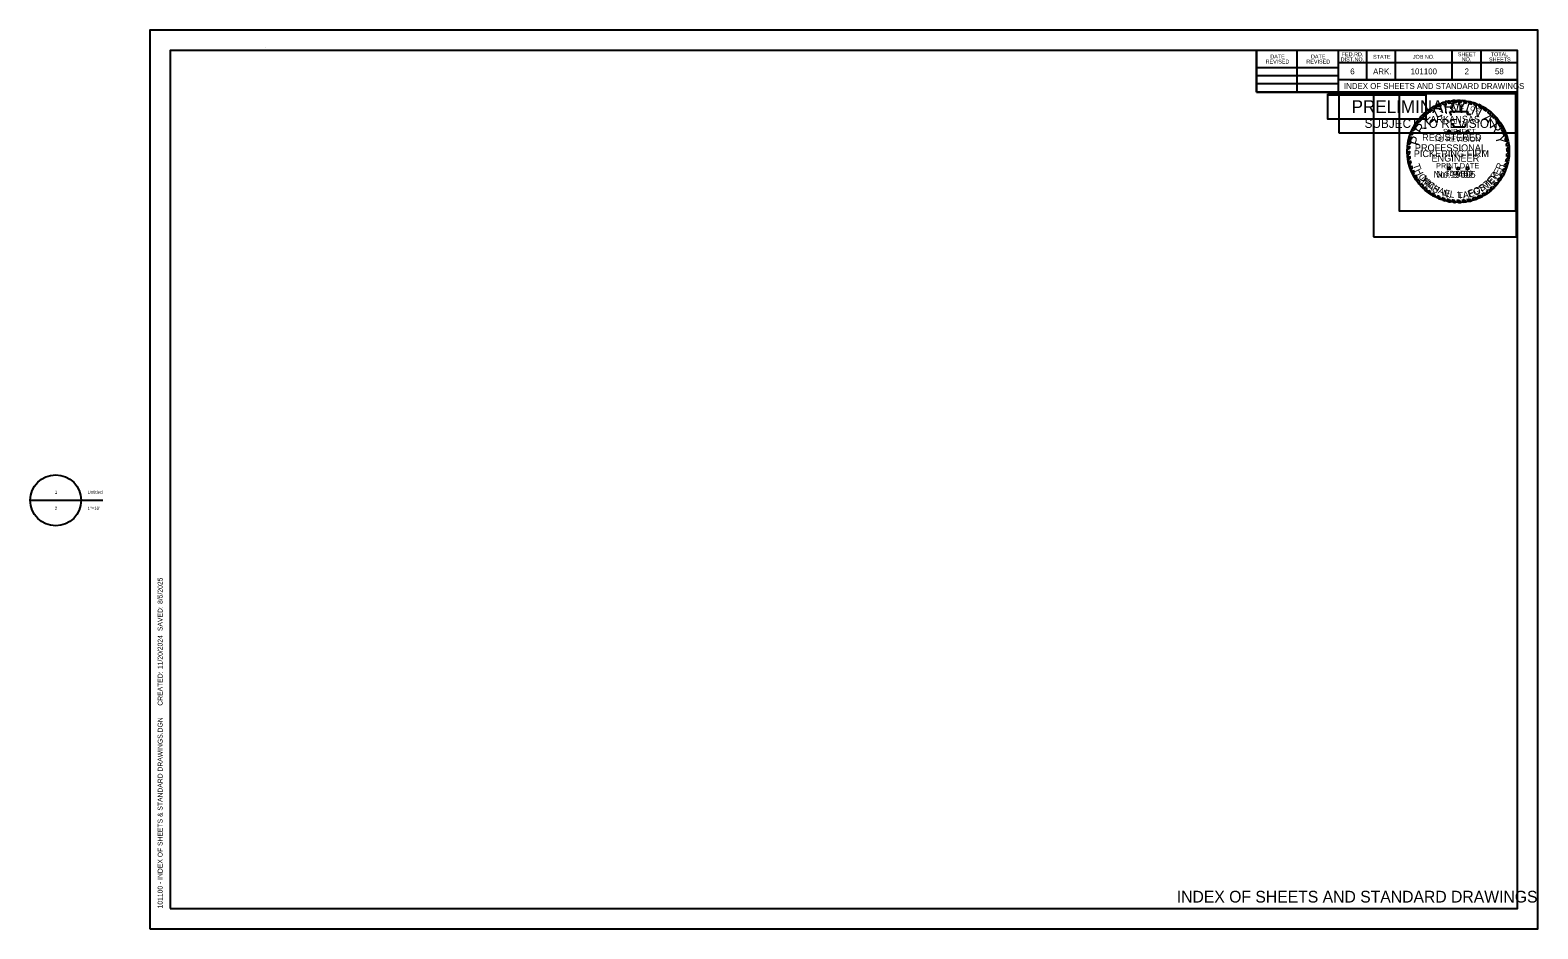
# Model space of a CAD drawing. Extents: x -0.12 to 1.42, y 0 to 0.92.
import ezdxf

# ---------------------------------------------------------------- set-up
doc = ezdxf.new("R2010")
doc.units = 0
for name, color, linetype in [('Default', 7, 'Continuous'), ('DSN_DRFT_Guideline-No-Plot', 7, 'Continuous'), ('SHET_Annotations', 7, 'Continuous'), ('SHET_Border-Lines', 7, 'Continuous'), ('SHET_Border-Text', 7, 'Continuous'), ('SHET_Stamp-Prelim', 7, 'Continuous'), ('SHET_Stamp-Seal', 7, 'Continuous'), ('STAMP_PE DIG SIG', 7, 'Continuous'), ('STAMP_PE_BACKGROUND', 7, 'Continuous'), ('STAMP_PE_FOSTER', 7, 'Continuous'), ('STAMP_PE_SEAL-INFO', 7, 'Continuous'), ('STAMP_PE_TAEGTMEYER', 7, 'Continuous'), ('STAMP_PRELIMINARY', 7, 'Continuous')]:
    doc.layers.add(name, color=color, linetype=linetype)

msp = doc.modelspace()

# ---------------------------------------------------------------- linework, layer by layer
at = {"layer": 'Default'}
for p, q in [((-0.1223, 0.4371), (-0.0702, 0.4371)), ((-0.096, 0.4371), (-0.0481, 0.4371))]:
    msp.add_line(p, q, dxfattribs=at)
msp.add_circle((-0.0962, 0.4371), 0.026, dxfattribs=at)
at = {"layer": 'DSN_DRFT_Guideline-No-Plot'}
msp.add_lwpolyline([(0, 0), (1.4167, 0), (1.4167, 0.9167), (0, 0.9167)], close=True, dxfattribs=at)
at = {"layer": 'SHET_Border-Lines'}
for p, q in [((0.1176, 0.8988), (0.1176, 0.8988)), ((0.1176, 0.8988), (0.1176, 0.8988)), ((1.1296, 0.8534), (1.1296, 0.8958)), ((1.1711, 0.8534), (1.1711, 0.8958)), ((1.2127, 0.8958), (1.2127, 0.8534)), ((1.2417, 0.8958), (1.2417, 0.866)), ((1.2712, 0.8958), (1.2712, 0.866)), ((1.3289, 0.8958), (1.3289, 0.866)), ((1.3584, 0.8958), (1.3584, 0.866)), ((1.1296, 0.8786), (1.2127, 0.8786)), ((1.3958, 0.8832), (1.2127, 0.8832)), ((1.3958, 0.8833), (1.3958, 0.8833)), ((1.1296, 0.8706), (1.2127, 0.8706)), ((1.1296, 0.8622), (1.2127, 0.8622)), ((1.3958, 0.866), (1.2127, 0.866)), ((1.2252, 0.866), (1.3958, 0.866)), ((1.3958, 0.8534), (1.1296, 0.8534))]:
    msp.add_line(p, q, dxfattribs=at)
for points in [[(0.0208, 0.0208), (1.3958, 0.0208), (1.3958, 0.8958), (0.0208, 0.8958)], [(1.1296, 0.8534), (1.3958, 0.8534), (1.3958, 0.8958), (1.1296, 0.8958)]]:
    msp.add_lwpolyline(points, close=True, dxfattribs=at)
at = {"layer": 'SHET_Stamp-Prelim'}
msp.add_lwpolyline([(1.2137, 0.8119), (1.3948, 0.8119), (1.3948, 0.8524), (1.2137, 0.8524)], close=True, dxfattribs=at)
at = {"layer": 'SHET_Stamp-Seal'}
msp.add_line((1.3219, 0.7895), (1.3219, 0.7895), dxfattribs=at)
msp.add_lwpolyline([(1.249, 0.7057), (1.3948, 0.7057), (1.3948, 0.8524), (1.249, 0.8524)], close=True, dxfattribs=at)
at = {"layer": 'STAMP_PE DIG SIG'}
msp.add_lwpolyline([(1.2022, 0.8508), (1.3022, 0.8508), (1.3022, 0.8258), (1.2022, 0.8258)], close=True, dxfattribs=at)
at = {"layer": 'STAMP_PE_BACKGROUND'}
for points in [[(1.2022, 0.8517), (1.3022, 0.8517), (1.3022, 0.8258), (1.2022, 0.8258)], [(1.3942, 0.8517), (1.275, 0.8517), (1.275, 0.7325), (1.3942, 0.7325)]]:
    msp.add_lwpolyline(points, close=True, dxfattribs=at)
at = {"layer": 'STAMP_PE_SEAL-INFO'}
for p, q in [((1.3002, 0.8313), (1.3028, 0.8306)), ((1.3021, 0.833), (1.3051, 0.8325)), ((1.3042, 0.8348), (1.3068, 0.8337)), ((1.3066, 0.8363), (1.309, 0.8352)), ((1.3087, 0.8377), (1.3112, 0.8365)), ((1.3112, 0.8391), (1.3138, 0.8378)), ((1.3137, 0.8403), (1.3158, 0.8387)), ((1.3165, 0.8415), (1.3181, 0.8397)), ((1.3184, 0.8422), (1.3206, 0.8405)), ((1.3217, 0.8432), (1.3233, 0.8413)), ((1.3239, 0.8438), (1.3259, 0.8418)), ((1.3266, 0.8443), (1.3283, 0.8422)), ((1.3269, 0.8337), (1.3456, 0.8337)), ((1.3276, 0.832), (1.3269, 0.8337)), ((1.3281, 0.8303), (1.3276, 0.832)), ((1.3295, 0.8447), (1.331, 0.8426)), ((1.3336, 0.8427), (1.3318, 0.8449)), ((1.3364, 0.8428), (1.3348, 0.845)), ((1.3389, 0.8426), (1.3375, 0.845)), ((1.3417, 0.8424), (1.3401, 0.8448)), ((1.3441, 0.842), (1.3427, 0.8445)), ((1.3456, 0.8337), (1.3443, 0.831)), ((1.3473, 0.8413), (1.3463, 0.8439)), ((1.3495, 0.8407), (1.3486, 0.8433)), ((1.352, 0.8399), (1.3512, 0.8426)), ((1.3544, 0.839), (1.3536, 0.8418)), ((1.357, 0.8379), (1.3564, 0.8406)), ((1.3594, 0.8366), (1.359, 0.8394)), ((1.3616, 0.8353), (1.3614, 0.8381)), ((1.364, 0.8337), (1.3639, 0.8366)), ((1.366, 0.8322), (1.3662, 0.8349)), ((1.3685, 0.8301), (1.3687, 0.8331)), ((1.3703, 0.8285), (1.3707, 0.8313)), ((1.2891, 0.8167), (1.2918, 0.8171)), ((1.2904, 0.8191), (1.2931, 0.8192)), ((1.2917, 0.8213), (1.2946, 0.8215)), ((1.293, 0.8232), (1.2959, 0.8232)), ((1.2946, 0.8253), (1.2977, 0.8254)), ((1.2965, 0.8276), (1.2994, 0.8274)), ((1.2983, 0.8295), (1.3014, 0.8293)), ((1.3282, 0.8297), (1.3281, 0.8303)), ((1.3293, 0.8201), (1.3291, 0.8213)), ((1.331, 0.8201), (1.3293, 0.8201)), ((1.331, 0.8177), (1.331, 0.8201)), ((1.3423, 0.8177), (1.331, 0.8177)), ((1.3424, 0.8196), (1.3423, 0.8177)), ((1.3429, 0.8213), (1.3424, 0.8196)), ((1.3443, 0.831), (1.3478, 0.831)), ((1.3478, 0.831), (1.347, 0.8297)), ((1.3723, 0.8264), (1.3727, 0.8294)), ((1.3738, 0.8247), (1.3746, 0.8273)), ((1.3756, 0.8223), (1.3764, 0.8251)), ((1.3769, 0.8206), (1.3779, 0.8232)), ((1.3786, 0.8178), (1.3796, 0.8205)), ((1.3797, 0.8157), (1.381, 0.8182)), ((1.381, 0.813), (1.3823, 0.8157)), ((1.2862, 0.8008), (1.2838, 0.7996)), ((1.2867, 0.8034), (1.2841, 0.802)), ((1.2847, 0.8048), (1.2873, 0.8059)), ((1.2853, 0.8071), (1.2879, 0.808)), ((1.2862, 0.8099), (1.2889, 0.8106)), ((1.287, 0.8121), (1.2898, 0.8129)), ((1.288, 0.8145), (1.2908, 0.8151)), ((1.3252, 0.8129), (1.3241, 0.8137)), ((1.3241, 0.8137), (1.3255, 0.8137)), ((1.3248, 0.8116), (1.3252, 0.8129)), ((1.3259, 0.8124), (1.3248, 0.8116)), ((1.3255, 0.8137), (1.3259, 0.815)), ((1.3259, 0.815), (1.3264, 0.8137)), ((1.327, 0.8116), (1.3259, 0.8124)), ((1.3264, 0.8137), (1.3277, 0.8137)), ((1.3277, 0.8137), (1.3266, 0.8129)), ((1.3266, 0.8129), (1.327, 0.8116)), ((1.3347, 0.8129), (1.3336, 0.8137)), ((1.3336, 0.8137), (1.335, 0.8137)), ((1.3343, 0.8116), (1.3347, 0.8129)), ((1.3354, 0.8124), (1.3343, 0.8116)), ((1.335, 0.8137), (1.3354, 0.815)), ((1.3354, 0.815), (1.3358, 0.8137)), ((1.3365, 0.8116), (1.3354, 0.8124)), ((1.3358, 0.8137), (1.3372, 0.8137)), ((1.3372, 0.8137), (1.3361, 0.8129)), ((1.3361, 0.8129), (1.3365, 0.8116)), ((1.3442, 0.8129), (1.3431, 0.8137)), ((1.3431, 0.8137), (1.3445, 0.8137)), ((1.3438, 0.8116), (1.3442, 0.8129)), ((1.3449, 0.8124), (1.3438, 0.8116)), ((1.3445, 0.8137), (1.3449, 0.815)), ((1.3449, 0.815), (1.3453, 0.8137)), ((1.346, 0.8116), (1.3449, 0.8124)), ((1.3453, 0.8137), (1.3467, 0.8137)), ((1.3467, 0.8137), (1.3456, 0.8129)), ((1.3456, 0.8129), (1.346, 0.8116)), ((1.3818, 0.8112), (1.3832, 0.8136)), ((1.3829, 0.8081), (1.3844, 0.8107)), ((1.3835, 0.8061), (1.3851, 0.8086)), ((1.3842, 0.8029), (1.386, 0.8054)), ((1.3846, 0.8008), (1.3866, 0.8028)), ((1.2857, 0.796), (1.2834, 0.7946)), ((1.2856, 0.7933), (1.2834, 0.7914)), ((1.2859, 0.7984), (1.2835, 0.7968)), ((1.2857, 0.791), (1.2835, 0.7892)), ((1.2858, 0.7882), (1.2838, 0.7862)), ((1.2861, 0.7858), (1.2842, 0.7837)), ((1.3846, 0.7855), (1.3871, 0.7867)), ((1.3849, 0.7876), (1.3874, 0.7891)), ((1.385, 0.798), (1.387, 0.7998)), ((1.3851, 0.7956), (1.3873, 0.7973)), ((1.3852, 0.7927), (1.3875, 0.7945)), ((1.3852, 0.7905), (1.3875, 0.792)), ((1.2866, 0.7833), (1.2847, 0.7812)), ((1.2871, 0.7809), (1.2854, 0.7786)), ((1.2878, 0.7784), (1.2861, 0.7761)), ((1.2886, 0.7761), (1.287, 0.7738)), ((1.2895, 0.7737), (1.288, 0.7713)), ((1.2905, 0.7715), (1.2892, 0.769)), ((1.3252, 0.7754), (1.3241, 0.7763)), ((1.3241, 0.7763), (1.3255, 0.7763)), ((1.3248, 0.7741), (1.3252, 0.7754)), ((1.3259, 0.7749), (1.3248, 0.7741)), ((1.3255, 0.7763), (1.3259, 0.7776)), ((1.3259, 0.7776), (1.3264, 0.7763)), ((1.327, 0.7741), (1.3259, 0.7749)), ((1.3264, 0.7763), (1.3277, 0.7763)), ((1.3277, 0.7763), (1.3266, 0.7754)), ((1.3266, 0.7754), (1.327, 0.7741)), ((1.3347, 0.7754), (1.3336, 0.7763)), ((1.3336, 0.7763), (1.335, 0.7763)), ((1.3343, 0.7741), (1.3347, 0.7754)), ((1.3354, 0.7749), (1.3343, 0.7741)), ((1.335, 0.7763), (1.3354, 0.7776)), ((1.3354, 0.7776), (1.3358, 0.7763)), ((1.3365, 0.7741), (1.3354, 0.7749)), ((1.3358, 0.7763), (1.3372, 0.7763)), ((1.3372, 0.7763), (1.3361, 0.7754)), ((1.3361, 0.7754), (1.3365, 0.7741)), ((1.3442, 0.7754), (1.3431, 0.7763)), ((1.3431, 0.7763), (1.3445, 0.7763)), ((1.3438, 0.7741), (1.3442, 0.7754)), ((1.3449, 0.7749), (1.3438, 0.7741)), ((1.3445, 0.7763), (1.3449, 0.7776)), ((1.3449, 0.7776), (1.3453, 0.7763)), ((1.346, 0.7741), (1.3449, 0.7749)), ((1.3453, 0.7763), (1.3467, 0.7763)), ((1.3467, 0.7763), (1.3456, 0.7754)), ((1.3456, 0.7754), (1.346, 0.7741)), ((1.3799, 0.7705), (1.3826, 0.7709)), ((1.3808, 0.7724), (1.3835, 0.7729)), ((1.382, 0.7753), (1.3847, 0.776)), ((1.3827, 0.7774), (1.3855, 0.7785)), ((1.3835, 0.7802), (1.3862, 0.7813)), ((1.3841, 0.7827), (1.3867, 0.7838)), ((1.2918, 0.769), (1.2907, 0.7662)), ((1.2931, 0.7667), (1.2921, 0.7641)), ((1.2942, 0.765), (1.2936, 0.7619)), ((1.2958, 0.7628), (1.2952, 0.7598)), ((1.2975, 0.7607), (1.297, 0.7578)), ((1.2992, 0.7588), (1.2988, 0.7559)), ((1.301, 0.757), (1.3008, 0.754)), ((1.3029, 0.7552), (1.3029, 0.7523)), ((1.3679, 0.7553), (1.3706, 0.7545)), ((1.3702, 0.7573), (1.3727, 0.7566)), ((1.3716, 0.7588), (1.3743, 0.7583)), ((1.3738, 0.7612), (1.3763, 0.7608)), ((1.3755, 0.7634), (1.3783, 0.7634)), ((1.3774, 0.7662), (1.3801, 0.7661)), ((1.3783, 0.7677), (1.3811, 0.768)), ((1.3049, 0.7536), (1.305, 0.7507)), ((1.3068, 0.7522), (1.307, 0.7493)), ((1.3092, 0.7506), (1.3095, 0.7478)), ((1.3111, 0.7495), (1.3117, 0.7466)), ((1.3138, 0.7481), (1.3147, 0.7452)), ((1.3159, 0.7471), (1.3169, 0.7443)), ((1.3187, 0.7461), (1.3198, 0.7433)), ((1.321, 0.7453), (1.3222, 0.7426)), ((1.3238, 0.7445), (1.325, 0.7419)), ((1.326, 0.7441), (1.3274, 0.7415)), ((1.3288, 0.7436), (1.3302, 0.7411)), ((1.3313, 0.7433), (1.3328, 0.7409)), ((1.334, 0.7432), (1.3356, 0.7409)), ((1.3365, 0.7432), (1.3384, 0.741)), ((1.3394, 0.7433), (1.3412, 0.7412)), ((1.3419, 0.7436), (1.344, 0.7416)), ((1.3444, 0.744), (1.3465, 0.7421)), ((1.3471, 0.7446), (1.3492, 0.7427)), ((1.3497, 0.7453), (1.352, 0.7436)), ((1.3524, 0.7462), (1.3549, 0.7447)), ((1.3548, 0.7471), (1.3571, 0.7456)), ((1.3573, 0.7483), (1.36, 0.7471)), ((1.3596, 0.7494), (1.3619, 0.7481)), ((1.3619, 0.7508), (1.3644, 0.7497)), ((1.3639, 0.7521), (1.3663, 0.751)), ((1.3664, 0.754), (1.369, 0.7532))]:
    msp.add_line(p, q, dxfattribs=at)
for radius, start, end in [(0.0521, 129.7326, 132.5376), (0.0498, 127.5297, 130.9683), (0.0521, 123.6199, 126.5906), (0.0498, 121.9746, 125.11), (0.0521, 117.6544, 120.8099), (0.0498, 115.6869, 119.1583), (0.0521, 111.3124, 114.7026), (0.0498, 110.3086, 113.1659), (0.0521, 105.2339, 109.0352), (0.0498, 104.0352, 107.3615), (0.0521, 99.7525, 102.7765), (0.0498, 98.258, 101.0329), (0.0521, 93.9381, 96.5517), (0.0498, 92.1102, 95.0367), (0.0521, 87.7298, 90.6707), (0.0498, 85.9628, 88.9097), (0.0521, 81.9732, 84.8236), (0.0498, 79.9264, 82.696), (0.0521, 75.3125, 77.9426), (0.0498, 73.5575, 76.2314), (0.0521, 69.6061, 72.3058), (0.0498, 67.6248, 70.504), (0.0521, 63.1329, 66.2704), (0.0498, 61.1558, 64.3784), (0.0521, 56.9003, 60.0942), (0.0498, 54.9238, 58.2702), (0.0498, 48.3016, 52.0395), (0.0521, 50.3492, 53.7159), (0.0521, 44.3405, 47.3929), (0.0521, 152.864, 155.5189), (0.0521, 147.0072, 149.899), (0.0498, 151.0315, 153.573), (0.0521, 141.6056, 144.4486), (0.0498, 145.0197, 148.2104), (0.0498, 139.301, 142.5873), (0.0521, 135.4021, 138.3031), (0.0498, 133.1331, 136.2562), (0.0498, 42.2212, 45.5512), (0.0498, 36.135, 39.5311), (0.0521, 38.1247, 41.2316), (0.0498, 29.9032, 33.6645), (0.0521, 31.9614, 35.4294), (0.0498, 23.7732, 27.2211), (0.0521, 25.9391, 29.0125), (0.0521, 170.0003, 172.6878), (0.0521, 164.3068, 166.894), (0.0521, 158.4077, 161.0701), (0.0498, 167.9048, 170.9039), (0.0498, 162.4331, 165.0013), (0.0498, 156.3402, 159.2319), (0.0498, 17.6802, 21.4251), (0.0521, 19.9538, 23.3141), (0.0498, 11.5444, 15.2364), (0.0498, 5.7599, 9.0606), (0.0521, 13.8421, 17.4447), (0.0521, 7.5852, 10.8621), (0.0521, 175.7409, 178.2066), (0.0521, 181.7251, 184.1626), (0.0521, 187.4204, 190.1927), (0.0498, 179.6454, 182.2633), (0.0498, 173.73, 176.4734), (0.0498, 185.4539, 188.234), (0.0498, 348.0778, 351.3435), (0.0498, 353.8632, 357.1274), (0.0498, 359.7329, 3.0639), (0.0521, 349.8305, 353.0885), (0.0521, 1.7215, 4.7268), (0.0521, 355.7156, 358.9569), (0.0521, 193.0369, 195.9973), (0.0521, 198.8967, 201.6281), (0.0498, 191.2274, 193.9858), (0.0498, 196.9675, 199.8353), (0.0521, 204.5479, 207.4328), (0.0498, 202.7761, 205.4791), (0.0498, 329.5549, 333.2076), (0.0498, 335.6038, 339.1858), (0.0521, 331.4037, 334.9332), (0.0498, 341.777, 345.0925), (0.0521, 337.3837, 340.9933), (0.0521, 343.8925, 347.035), (0.0521, 210.8636, 213.6571), (0.0498, 208.7883, 211.7934), (0.0521, 216.6115, 219.491), (0.0498, 214.1838, 217.2747), (0.0521, 222.48, 225.3801), (0.0498, 220.3909, 223.3056), (0.0498, 226.2494, 229.2407), (0.0498, 310.7744, 314.3161), (0.0521, 312.4518, 315.6633), (0.0498, 316.6531, 320.3711), (0.0521, 318.2846, 321.8043), (0.0498, 323.5851, 327.4407), (0.0521, 325.4405, 328.9872), (0.0521, 228.3665, 231.348), (0.0498, 232.229, 234.9336), (0.0521, 234.295, 236.9452), (0.0498, 238.2223, 240.8353), (0.0521, 240.1977, 242.8613), (0.0498, 244.3204, 246.9486), (0.0521, 246.576, 249.1558), (0.0498, 250.3491, 253.1216), (0.0521, 252.5967, 255.3252), (0.0498, 256.505, 259.1192), (0.0521, 258.4433, 261.1398), (0.0498, 262.3783, 265.2012), (0.0521, 264.1978, 267.1009), (0.0498, 268.3215, 271.277), (0.0521, 270.2548, 273.3361), (0.0498, 274.6157, 277.4486), (0.0521, 276.4239, 279.4357), (0.0498, 280.3459, 283.5814), (0.0521, 282.3199, 285.3702), (0.0498, 286.6423, 289.9783), (0.0521, 288.5709, 291.9733), (0.0498, 292.8745, 296.1185), (0.0521, 294.6481, 298.2166), (0.0498, 299.0768, 302.1724), (0.0521, 300.621, 303.8703), (0.0498, 304.823, 308.5143), (0.0521, 306.3721, 310.208)]:
    msp.add_arc((1.3354, 0.793), radius, start, end, dxfattribs=at)
at = {"layer": 'STAMP_PRELIMINARY'}
msp.add_circle((1.3354, 0.793), 0.0521, dxfattribs=at)

# ---------------------------------------------------------------- texts
at = {"layer": 'Default'}
for s, p in [('1', (-0.0971, 0.4437)), ('Untitled', (-0.0637, 0.4437)), ('2', (-0.0972, 0.4273)), ('1"=10\'', (-0.0637, 0.4273))]:
    msp.add_text(s, height=0.00328, dxfattribs=at).set_placement(p)
at = {"layer": 'SHET_Annotations'}
for s, height, p in [('6', 0.006, (1.2252, 0.8716)), ('ARK.', 0.006, (1.2485, 0.8716)), ('101100', 0.006, (1.2869, 0.8716)), ('2', 0.006, (1.3419, 0.8716)), ('58', 0.006, (1.3729, 0.8717)), ('INDEX OF SHEETS AND STANDARD DRAWINGS', 0.006, (1.2188, 0.8567)), ('INDEX OF SHEETS AND STANDARD DRAWINGS', 0.012, (1.0481, 0.0268))]:
    msp.add_text(s, height=height, dxfattribs=at).set_placement(p)
at = {"layer": 'SHET_Border-Text'}
for s, p in [('FED.RD.', (1.2165, 0.8901)), ('SHEET', (1.335, 0.8901)), ('TOTAL', (1.3686, 0.8901)), ('REVISED', (1.1388, 0.8826)), ('DATE', (1.1436, 0.8878)), ('REVISED', (1.1804, 0.8826)), ('DATE', (1.1851, 0.8878)), ('DIST.NO.', (1.2154, 0.8849)), ('STATE', (1.2485, 0.8875)), ('JOB NO.', (1.2891, 0.8875)), ('NO.', (1.339, 0.8849)), ('SHEETS', (1.3668, 0.8849))]:
    msp.add_text(s, height=0.004, dxfattribs=at).set_placement(p)
for s, p in [('8/5/2025', (0.0129, 0.3314)), ('  SAVED: ', (0.0129, 0.2999)), ('11/20/2024', (0.0129, 0.265)), ('     CREATED: ', (0.0129, 0.218)), ('101100 - INDEX OF SHEETS & STANDARD DRAWINGS.DGN', (0.0129, 0.0208))]:
    msp.add_text(s, height=0.005, rotation=90, dxfattribs=at).set_placement(p)
at = {"layer": 'SHET_Stamp-Prelim'}
for s, height, p in [('PRELIMINARY', 0.013, (1.2266, 0.8322)), ('SUBJECT TO REVISION', 0.009, (1.2398, 0.817))]:
    msp.add_text(s, height=height, dxfattribs=at).set_placement(p)
at = {"layer": 'STAMP_PE_FOSTER'}
msp.add_text('No. 9402', height=0.00698, dxfattribs=at).set_placement((1.313, 0.7661))
for s, rotation, p in [('R', 54.5031, (1.373, 0.764)), ('M', 308.339, (1.297, 0.7652)), ('I', 314.1842, (1.3014, 0.7599)), ('C', 319.8733, (1.3034, 0.7579)), ('H', 327.7235, (1.3086, 0.7538)), ('A', 335.7276, (1.3141, 0.7506)), ('E', 343.5779, (1.3204, 0.748)), ('F', 15.8691, (1.3468, 0.7469)), ('O', 23.719, (1.3526, 0.7487)), ('S', 31.7234, (1.3588, 0.7517)), ('T', 39.4194, (1.3641, 0.7552)), ('E', 46.9613, (1.3689, 0.7594)), ('L', 350.8115, (1.3263, 0.7464)), ('L', 1.2666, (1.3349, 0.7455)), ('.', 6.8035, (1.3408, 0.7459))]:
    msp.add_text(s, height=0.0067, rotation=rotation, dxfattribs=at).set_placement(p)
at = {"layer": 'STAMP_PE_SEAL-INFO'}
for s, rotation, p in [('S', 23.5541, (1.3164, 0.8327)), ('T', 16.311, (1.3216, 0.8347)), ('A', 9.0679, (1.3269, 0.8361)), ('T', 1.8248, (1.3325, 0.8369)), ('E', 355.2002, (1.3375, 0.8369)), ('O', 342.2506, (1.3472, 0.8354)), ('F', 335.0075, (1.3526, 0.8335))]:
    msp.add_text(s, height=0.00436, rotation=rotation, dxfattribs=at).set_placement(p)
for s, height, p in [('ARKANSAS', 0.00698, (1.3069, 0.8223)), ('PROFESSIONAL', 0.006983, (1.2911, 0.7932)), ('REGISTERED', 0.00698, (1.2986, 0.8038)), ('ENGINEER', 0.00698, (1.3081, 0.7826))]:
    msp.add_text(s, height=height, dxfattribs=at).set_placement(p)
at = {"layer": 'STAMP_PE_TAEGTMEYER'}
for s, rotation, p in [('T', 289.646, (1.289, 0.7791)), ('H', 296.7339, (1.291, 0.7736)), ('O', 303.7708, (1.2943, 0.7674)), ('Y', 53.9986, (1.3733, 0.7628)), ('E', 63.0984, (1.377, 0.768)), ('R', 69.57, (1.3798, 0.7735)), ('M', 314.2033, (1.298, 0.7621)), ('A', 321.0594, (1.3034, 0.7567)), ('S', 327.8239, (1.308, 0.7531)), ('G', 23.3052, (1.3522, 0.7475)), ('T', 31.466, (1.3583, 0.7503)), ('M', 39.3, (1.3633, 0.7533)), ('E', 46.8094, (1.3692, 0.7582)), ('N', 344.2727, (1.3186, 0.7474)), ('.', 350.6464, (1.3254, 0.7456)), ('T', 3.0061, (1.3347, 0.7445)), ('A', 8.9826, (1.3405, 0.7448)), ('E', 17.6836, (1.3463, 0.7457))]:
    msp.add_text(s, height=0.00698, rotation=rotation, dxfattribs=at).set_placement(p)
msp.add_text('No. 19605', height=0.00698, dxfattribs=at).set_placement((1.3101, 0.7661))
at = {"layer": 'STAMP_PRELIMINARY'}
for s, rotation, p in [('E', 42.3578, (1.3048, 0.8192)), ('L', 25.513, (1.3131, 0.8266)), ('I', 12.5248, (1.3217, 0.8309)), ('M', 3.1074, (1.3278, 0.8326)), ('I', 342.3164, (1.3416, 0.833)), ('N', 333.9382, (1.3478, 0.8315)), ('R', 56.2292, (1.2984, 0.8095)), ('A', 315.6579, (1.3591, 0.8257)), ('R', 301.3831, (1.3668, 0.8184)), ('P', 73.913, (1.2953, 0.7982)), ('Y', 283.2593, (1.3729, 0.8084))]:
    msp.add_text(s, height=0.0101, rotation=rotation, dxfattribs=at).set_placement(p)
for s, height, p in [('SUBJECT', 0.00536, (1.3198, 0.8106)), ('TO REVISION', 0.005363, (1.3105, 0.8028)), ('PICKERING FIRM', 0.006983, (1.29, 0.7872)), ('PRINT DATE', 0.00536, (1.3128, 0.7757)), ('$DATE$', 0.00536, (1.3222, 0.768))]:
    msp.add_text(s, height=height, dxfattribs=at).set_placement(p)

doc.saveas('drawing.dxf')
